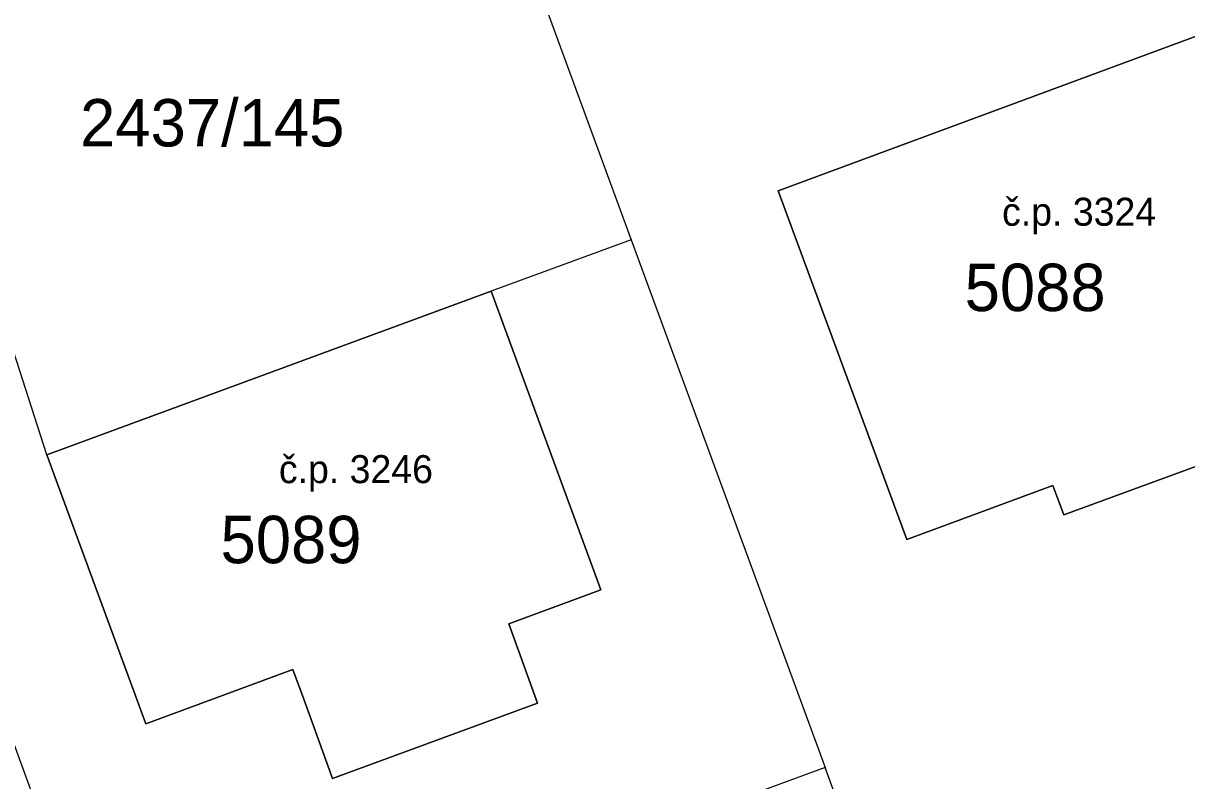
# Model space of a CAD drawing. Extents: x -566117 to -565580, y -1202428 to -1201938.
# Drawn here: x -565856.36 to -565829.36, y -1202054.29 to -1202036.71 of the extents above; entities that cross this region are included whole.
import ezdxf

# ---------------------------------------------------------------- set-up
doc = ezdxf.new("R2010")
doc.units = 0
for name, color, linetype in [('BUOVY_NEMĚŘ', 7, 'Continuous'), ('Implicitní', 7, 'Continuous'), ('Katastr', 7, 'Continuous'), ('Zpevněné plohy', 7, 'Continuous'), ('Číslo popisné', 7, 'Continuous')]:
    doc.layers.add(name, color=color, linetype=linetype)

# ---------------------------------------------------------------- blocks, each defined once
blk = doc.blocks.new('A$C69D74C1E')
at = {"layer": 'Katastr'}
for p, q in [((218.72, 37.49), (222.68, 26.7)), ((222.68, 26.7), (227.18, 14.46)), ((221.98, 18.58), (219.43, 25.51)), ((209.12, 21.71), (211.42, 15.47)), ((206.27, 20.67), (210.24, 9.87)), ((219.84, 17.79), (221.98, 18.58)), ((220.51, 15.95), (219.84, 17.79)), ((211.42, 15.47), (214.83, 16.73)), ((214.83, 16.73), (215.08, 16.04)), ((215.08, 16.04), (215.75, 14.2)), ((215.75, 14.2), (220.51, 15.95)), ((227.18, 14.46), (210.77, 8.43)), ((229.06, 9.35), (227.18, 14.46))]:
    blk.add_line(p, q, dxfattribs=at)
for points in [[(222.68, 26.7), (219.43, 25.51), (209.12, 21.71), (205.59, 32.66)], [(229.08, 19.75), (232.47, 21), (232.72, 20.32), (239.62, 22.85), (236.38, 31.64), (226.09, 27.84), (229.08, 19.75)]]:
    blk.add_lwpolyline(points, dxfattribs=at)
for s, p in [('2437/145', (209.89, 28.867)), ('5088', (230.42, 25.047)), ('5089', (213.15, 19.197))]:
    blk.add_text(s, height=1.1, dxfattribs=at).set_placement(p)

msp = doc.modelspace()

# ---------------------------------------------------------------- linework, layer by layer
at = {"layer": 'BUOVY_NEMĚŘ'}
msp.add_lwpolyline([(-565825.31, -1202045.59), (-565832.21, -1202048.12), (-565832.46, -1202047.44), (-565835.849, -1202048.693), (-565838.84, -1202040.6), (-565828.55, -1202036.8)], close=True, dxfattribs=at)
for points in [[(-565835.85, -1202048.69), (-565838.84, -1202040.6), (-565828.55, -1202036.8), (-565825.31, -1202045.59), (-565832.21, -1202048.12), (-565832.46, -1202047.44), (-565835.849, -1202048.693)], [(-565855.81, -1202046.73), (-565845.5, -1202042.93), (-565842.95, -1202049.86), (-565845.09, -1202050.65), (-565844.42, -1202052.49), (-565849.18, -1202054.24), (-565849.85, -1202052.4), (-565850.1, -1202051.71), (-565853.51, -1202052.97), (-565855.81, -1202046.73)]]:
    msp.add_lwpolyline(points, dxfattribs=at)
at = {"layer": 'Zpevněné plohy'}
for points in [[(-566046.233, -1202095.491), (-566045.931, -1202095.393), (-566043.978, -1202094.752), (-566040.389, -1202093.195), (-566035.531, -1202091.756), (-566028.975, -1202089.449), (-566022.404, -1202086.74), (-566013.877, -1202083.764), (-566006.988, -1202080.967), (-565999.231, -1202078.336), (-565993.39, -1202076.098), (-565982.391, -1202071.759), (-565967.94, -1202066.641), (-565949.498, -1202059.811), (-565935.388, -1202054.572), (-565926.049, -1202051.077), (-565917.958, -1202048.181), (-565909.827, -1202045.163), (-565898.95, -1202041.321), (-565888.732, -1202037.388), (-565879.759, -1202034.036), (-565869.081, -1202030.224), (-565859.242, -1202026.317), (-565849.297, -1202023.069), (-565843.932, -1202020.848), (-565836.631, -1202018.501), (-565830.04, -1202016.01), (-565822.89, -1202013.251), (-565816.476, -1202011.009), (-565808.989, -1202007.913), (-565802.143, -1202004.887), (-565798.059, -1202002.759), (-565793.947, -1202000.116), (-565789.34, -1201997.072), (-565785.134, -1201994.185), (-565781.539, -1201991.969), (-565778.045, -1201989.73), (-565773.319, -1201986.775), (-565768.281, -1201983.714), (-565761.544, -1201979.725), (-565754.374, -1201977.005), (-565748.201, -1201974.518), (-565743.713, -1201972.786), (-565741.115, -1201971.759), (-565739.444, -1201971.098)], [(-565976.764, -1202074.599), (-565975.068, -1202073.996), (-565970.908, -1202072.515), (-565960.65, -1202068.538), (-565946.466, -1202063.528), (-565932.832, -1202058.326), (-565923.028, -1202054.759), (-565915.71, -1202052.273), (-565903.782, -1202047.572), (-565889.735, -1202042.655), (-565875.782, -1202037.425), (-565865.226, -1202033.562), (-565857.124, -1202030.559), (-565849.222, -1202027.615), (-565843.807, -1202025.74), (-565838.67, -1202023.909), (-565834.175, -1202022.242), (-565830.509, -1202020.913), (-565828.358, -1202020.134)]]:
    msp.add_open_spline(points, degree=3, dxfattribs=at)

# ---------------------------------------------------------------- block references
at = {"layer": 'Implicitní'}
msp.add_blockref('A$C69D74C1E', (-566064.93, -1202068.44), dxfattribs=at)

# ---------------------------------------------------------------- texts
at = {"layer": 'Číslo popisné'}
for s, p in [('č.p. 3324', (-565833.641, -1202041.413)), ('č.p. 3246', (-565850.426, -1202047.385))]:
    msp.add_text(s, height=0.65, dxfattribs=at).set_placement(p)

doc.saveas('drawing.dxf')
